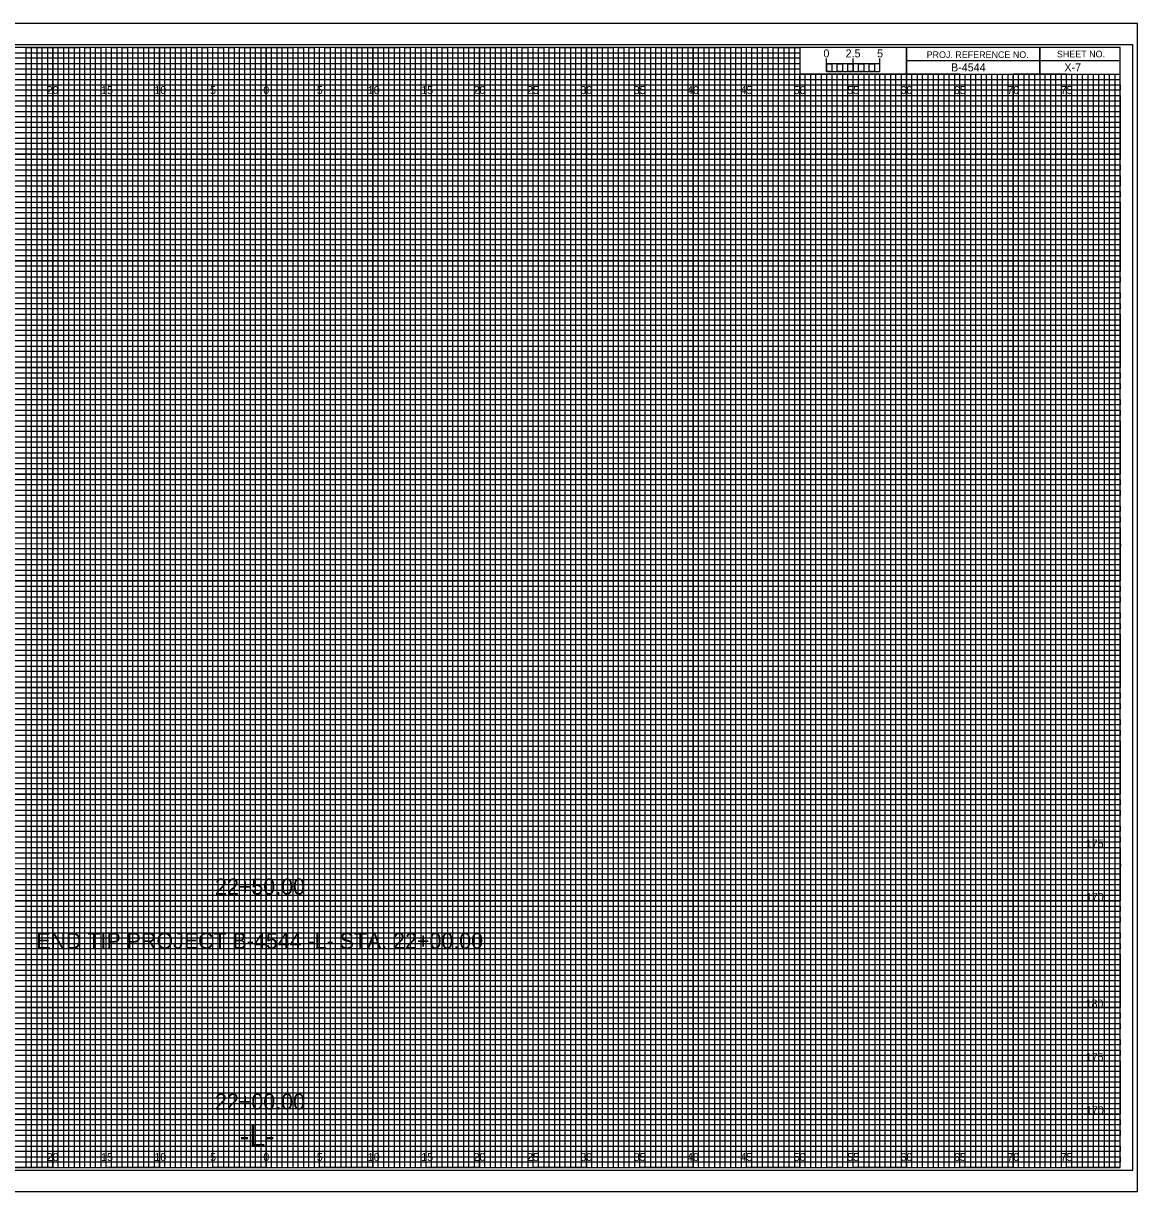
# Model space of a CAD drawing. Extents: x -7 to 162, y -2 to 767.
# Drawn here: x 57.2 to 161.7, y 657.8 to 767.2 of the extents above; entities that cross this region are included whole.
import ezdxf

# ---------------------------------------------------------------- set-up
doc = ezdxf.new("R2010")
doc.units = 0
for name, color, linetype in [('Exist CMT Pavement', 7, 'Continuous'), ('Exist Cross Section Cell', 7, 'Continuous'), ('Exist XS Ground Line', 7, 'Continuous'), ('Prop CMT Pvmt Course 1', 7, 'Continuous'), ('Prop CMT Pvmt Course 1 Wedge', 7, 'Continuous'), ('Prop CMT Pvmt Course 2', 7, 'Continuous'), ('Prop CMT Pvmt Course 2 Wedge', 7, 'Continuous'), ('Prop CMT Pvmt Course 3', 7, 'Continuous'), ('Prop CMT Pvmt Course 3 Wedge', 7, 'Continuous'), ('Prop CMT Pvmt Surface', 7, 'Continuous'), ('Prop CMT Pvmt Surface Shoulder', 7, 'Continuous'), ('Prop CMT Shld Paved Course 1', 7, 'Continuous'), ('Prop CMT Shld Paved Course 2', 7, 'Continuous'), ('Prop CMT Shld Paved Course 3', 7, 'Continuous'), ('Prop CMT Slope Grass', 7, 'Continuous'), ('Prop CMT Subgrade Earthwork', 7, 'Continuous'), ('Scratch_Level_0', 7, 'Continuous')]:
    doc.layers.add(name, color=color, linetype=linetype)

msp = doc.modelspace()

# ---------------------------------------------------------------- linework, layer by layer
at = {"layer": 'Prop CMT Pvmt Course 1'}
for p, q in [((0, 764.5), (130, 764.5)), ((130, 764.5), (130, 763.99)), ((130, 763.99), (0, 763.99)), ((0, 763.5), (130, 763.5)), ((130, 763.5), (130, 762.95)), ((130, 762.95), (0, 762.95)), ((0, 762), (160, 762))]:
    msp.add_line(p, q, dxfattribs=at)
for points in [[(0, 761.5), (135, 761.5), (160, 761.5), (160, 761), (0, 761)], [(0, 760.5), (160, 760.5), (160, 759.5), (0, 759.5)], [(0, 759), (160, 759), (160, 758.5), (0, 758.49)], [(0, 758), (160, 758), (160, 757), (0, 757)], [(0, 756.5), (160, 756.5), (160, 756), (0, 756)], [(0, 755.5), (160, 755.5), (160, 754.5), (0, 754.5)], [(0, 754), (160, 754), (160, 753.5), (0, 753.5)], [(0, 753), (160, 753), (160, 752), (0, 752)], [(0, 751.5), (160, 751.5), (160, 751), (0, 751)], [(0, 750.5), (160, 750.5), (160, 749.5), (0, 749.5)], [(0, 749), (160, 749), (160, 748.5), (0, 748.5)], [(0, 748), (160, 748), (160, 746.98), (160, 746.5), (160, 746), (0, 746)], [(0, 747), (160, 747), (160, 746.5), (0, 746.5)], [(0, 745.5), (160, 745.5), (160, 744.5), (0, 744.51)], [(0, 744.51), (160, 744.5), (160, 744), (0, 744)], [(0, 743.5), (160, 743.5), (160, 743), (0, 743)], [(0, 742), (160, 742), (160, 741.5), (0, 741.5)], [(0, 741), (160, 741), (160, 740.5), (0, 740.5)], [(-0.04, 739.45), (160, 739.45), (160, 738.94), (-0.04, 738.94)], [(0, 738.5), (160, 738.5), (160, 738), (0, 738)], [(0, 737), (160, 737), (160, 736.5), (0, 736.5)], [(0, 736), (160, 736), (160, 735.5), (0, 735.5)], [(0, 734.5), (160, 734.5), (160, 734), (0, 734)], [(0, 733.5), (160, 733.5), (160, 733), (0, 733)], [(0, 732), (160, 732), (160, 731.5), (0, 731.5)], [(0, 731), (160, 731), (160, 730.5), (0, 730.5)], [(0, 729.5), (160, 729.5), (160, 728.99), (0, 729)], [(0, 728.5), (160, 728.5), (160, 728), (0, 728)], [(0, 727), (160, 727), (160, 726.5), (0, 726.5)], [(0, 726), (160, 726), (160, 725.5), (0, 725.5)], [(0, 724.5), (160, 724.5), (160, 724), (0, 724)], [(0, 723.5), (160, 723.5), (160, 723), (0, 723)], [(0, 722), (160, 722), (160, 721.5), (0, 721.5)], [(0, 721), (160, 721), (160, 720.5), (0, 720.5)], [(0, 719.5), (160, 719.5), (160, 719), (0, 719)], [(0, 718.5), (160.03, 718.46), (160, 718), (0, 718)], [(0, 717), (160, 717), (160, 716.5), (0, 716.5)], [(0, 716), (160, 716), (160, 715.5), (0, 715.5)], [(0, 714.5), (160, 714.5), (160, 714), (0, 714)], [(0, 713.5), (160, 713.5), (160, 713), (0, 713)], [(0, 712), (160, 712), (160, 711.5), (0, 711.5)], [(0, 711), (160, 711), (160, 710.5), (0, 710.5)], [(0, 709.5), (160, 709.5), (160, 709), (0, 709)], [(0, 708.5), (160, 708.5), (160, 708), (0, 708)], [(0, 707), (160, 707), (160, 706.5), (0, 706.5)], [(0, 706), (160, 706), (160, 705.5), (0, 705.5)], [(0, 704.5), (160, 704.5), (160, 704), (0, 704)], [(0, 703.5), (160, 703.5), (160, 703), (0, 703)], [(0, 702), (160, 702), (160, 701.5), (0, 701.5)], [(0, 701), (160, 701), (160, 700.5), (0, 700.5)], [(0, 699.5), (160, 699.5), (160, 698.99), (0, 699)], [(0, 698.5), (160, 698.5), (160, 698), (0, 698)], [(0, 697), (160, 697), (160, 696.5), (0, 696.5)], [(0, 696), (160, 696), (160, 695.5), (0, 695.5)], [(0, 694.5), (160, 694.5), (160, 694), (0, 694)], [(0, 693.5), (160, 693.5), (160, 693), (0, 693)], [(0, 692), (160, 692), (160, 691.5), (0, 691.5)], [(0, 691), (160, 691), (160, 690.5), (0, 690.5)], [(0, 689.5), (160, 689.5), (160, 689), (0, 689)], [(0, 688.5), (160.03, 688.46), (160, 688), (0, 688)], [(0, 687), (160, 687), (160, 686.5), (0, 686.5)], [(0, 686), (160, 686), (160, 685.5), (0, 685.5)], [(0, 684.5), (160, 684.5), (160, 684), (0, 684)], [(0, 683.5), (160, 683.5), (160, 683), (0, 683)], [(0, 682), (160, 682), (160, 681.5), (0, 681.5)], [(0, 681), (160, 681), (160, 680.5), (0, 680.5)], [(0, 679.5), (160, 679.5), (160, 679), (0, 679)], [(0, 678.5), (160, 678.5), (160, 678), (0, 678)], [(0, 677), (160, 677), (160, 676.5), (0, 676.5)], [(0, 676), (160, 676), (160, 675.5), (0, 675.5)], [(0, 674.5), (160, 674.5), (160, 674), (0, 674)], [(0, 673.5), (160, 673.5), (160, 673), (0, 673)], [(0, 672), (160, 672), (160, 671.5), (0, 671.5)], [(0, 671), (160, 671), (160, 670.5), (0, 670.5)], [(0, 669.5), (160, 669.5), (160, 669), (0, 669)], [(0, 668.5), (160, 668.5), (160, 668), (0, 668)], [(0, 667), (160, 667), (160, 666.5), (0, 666.5)], [(0, 666), (160, 666), (160, 665.5), (0, 665.5)], [(0, 664.5), (160, 664.5), (160, 664), (0, 664)], [(0, 663.5), (160, 663.5), (160, 663), (0, 663)], [(0, 662), (160, 662), (160, 661.5), (0, 661.5)], [(0, 661), (160, 661), (160, 660.5), (0, 660.5)]]:
    msp.add_lwpolyline(points, dxfattribs=at)
at = {"layer": 'Prop CMT Pvmt Course 2'}
for p, q in [((60, 660), (60, 765)), ((65, 660), (65, 765)), ((70, 660), (70, 765)), ((75, 660), (75, 765)), ((80, 660), (80, 765)), ((85, 660), (85, 765)), ((90, 660), (90, 765)), ((95, 660), (95, 765)), ((100, 660), (100, 765)), ((105, 660), (105, 765)), ((110, 660), (110, 765)), ((115, 660), (115, 765)), ((120, 660), (120, 765)), ((125, 660), (125, 765)), ((130, 660), (130, 762.34)), ((135, 660), (135, 762.34)), ((140, 660), (140, 762.34)), ((145, 660), (145, 762.34)), ((150, 660), (150, 762.34)), ((155, 660), (155, 762.34)), ((0, 760), (160, 760)), ((0, 755), (160, 755)), ((0, 750), (160, 750)), ((0, 745), (160, 745)), ((0, 740), (160, 740)), ((0, 735), (160, 735)), ((0, 730), (160, 730)), ((0, 725), (160, 725)), ((0, 720), (160, 720)), ((0, 715), (160, 715)), ((0, 710), (160, 710)), ((0, 705), (160, 705)), ((0, 700), (160, 700)), ((0, 695), (160, 695)), ((0, 690), (160, 690)), ((0, 685), (160, 685)), ((0, 680), (160, 680)), ((0, 675), (160, 675)), ((0, 670), (160, 670)), ((0, 665), (160, 665))]:
    msp.add_line(p, q, dxfattribs=at)
at = {"layer": 'Prop CMT Pvmt Course 3'}
for p, q in [((161.65, 767.25), (-6.7, 767.25)), ((-6.7, 657.75), (161.65, 657.75))]:
    msp.add_line(p, q, dxfattribs=at)
at = {"layer": 'Prop CMT Pvmt Surface Shoulder'}
for points in [[(52.5, 660), (57.5, 660), (57.5, 765), (62.5, 765), (62.5, 660), (67.5, 660), (67.5, 765), (72.5, 765), (72.5, 660), (77.5, 660), (77.5, 765), (82.5, 765), (82.5, 660), (87.5, 660), (87.5, 765), (92.5, 765), (92.5, 660), (97.5, 660), (97.5, 765), (102.5, 765), (102.5, 660), (107.5, 660), (107.5, 765), (112.5, 765), (112.5, 660), (117.5, 660), (117.5, 765), (122.5, 765), (122.5, 660), (127.5, 660), (127.5, 765), (129.97, 765), (130, 765), (130, 762.5), (132.5, 762.5), (132.5, 660), (137.5, 660), (137.5, 762.5), (142.5, 762.5), (142.5, 660), (147.5, 660), (147.5, 762.5), (152.5, 762.5), (152.5, 660), (157.5, 660), (157.5, 762.5)], [(0, 762.5), (137.5, 762.5)], [(0, 752.5), (160, 752.5), (160, 757.5), (0, 757.5)], [(0, 742.5), (160, 742.5), (160, 747.5), (0, 747.5)], [(0, 732.5), (160, 732.5), (160, 737.5), (0, 737.5)], [(0, 722.5), (160, 722.5), (160, 727.5), (0, 727.5)], [(0, 712.5), (160, 712.5), (160, 717.5), (0, 717.5)], [(0, 702.5), (160, 702.5), (160, 707.5), (0, 707.5)], [(0, 692.5), (160, 692.5), (160, 697.5), (0, 697.5)], [(0, 682.5), (160, 682.5), (160, 687.5), (0, 687.5)], [(0, 672.5), (160, 672.5), (160, 677.5), (0, 677.5)], [(0, 662.5), (160, 662.5), (160, 667.5), (0, 667.5)]]:
    msp.add_lwpolyline(points, dxfattribs=at)
at = {"layer": 'Prop CMT Shld Paved Course 1'}
for p, q in [((132.5, 762.75), (132.5, 763.95)), ((132.5, 763.45), (132.5, 763.95)), ((135, 762.75), (135, 763.95)), ((137.5, 762.75), (137.5, 763.95)), ((137.5, 763.45), (137.5, 763.95))]:
    msp.add_line(p, q, dxfattribs=at)
for points in [[(137.5, 763.45), (132.5, 763.45), (132.5, 762.75), (137.5, 762.75)], [(132.5, 763.45), (133, 763.45), (133, 762.75), (132.5, 762.75)], [(133.5, 763.45), (134, 763.45), (134, 762.75), (133.5, 762.75)], [(134.5, 763.45), (135, 763.45), (135, 762.75), (134.5, 762.75)], [(135.5, 763.45), (136, 763.45), (136, 762.75), (135.5, 762.75)], [(136.5, 763.45), (137, 763.45), (137, 762.75), (136.5, 762.75)]]:
    msp.add_lwpolyline(points, close=True, dxfattribs=at)
at = {"layer": 'Prop CMT Shld Paved Course 2'}
msp.add_lwpolyline([(-6.7, 657.75), (161.65, 657.75), (161.65, 767.25), (-6.7, 767.25)], close=True, dxfattribs=at)
at = {"layer": 'Prop CMT Shld Paved Course 3'}
msp.add_lwpolyline([(-5.4, 659.75), (161.2, 659.75), (161.2, 765.25), (-5.4, 765.25)], close=True, dxfattribs=at)
at = {"layer": 'Prop CMT Slope Grass'}
for p, q in [((133.5, 762.5), (133, 762.5)), ((133, 762.5), (133, 660)), ((133.5, 660), (133.5, 762.5)), ((134.5, 762.5), (134, 762.5)), ((134, 762.5), (134, 660)), ((134.5, 660), (134.5, 762.5)), ((133, 660), (132.5, 660)), ((134, 660), (133.5, 660))]:
    msp.add_line(p, q, dxfattribs=at)
for points in [[(57.5, 660), (58, 660), (58, 765), (58.5, 765), (58.5, 660)], [(58.5, 660), (59, 660), (59, 765), (59.5, 765), (59.5, 660)], [(60, 660), (60.5, 660), (60.5, 765), (61, 765), (61, 660)], [(61, 660), (61.5, 660), (61.5, 765), (62, 765), (62, 660)], [(62.5, 660), (63, 660), (63, 765), (63.5, 765), (63.5, 660)], [(63.5, 660), (64, 660), (64, 765), (64.5, 765), (64.5, 660)], [(65, 660), (65.5, 660), (65.5, 765), (66, 765), (66, 660)], [(66, 660), (66.5, 660), (66.5, 765), (67, 765), (67, 660)], [(67.5, 660), (68, 660), (68, 765), (68.5, 765), (68.5, 660)], [(68.5, 660), (69, 660), (69, 765), (69.5, 765), (69.5, 660)], [(70, 660), (70.5, 660), (70.5, 765), (71, 765), (71, 660)], [(71, 660), (71.5, 660), (71.5, 765), (72, 765), (72, 660)], [(72.5, 660), (73, 660), (73, 765), (73.5, 765), (73.5, 660)], [(73.5, 660), (74, 660), (74, 765), (74.5, 765), (74.5, 660)], [(75, 660), (75.5, 660), (75.5, 765), (76, 765), (76, 660)], [(76, 660), (76.5, 660), (76.5, 765), (77, 765), (77, 660)], [(77.5, 660), (78, 660), (78, 765), (78.5, 765), (78.5, 660)], [(78.5, 660), (79, 660), (79, 765), (79.5, 765), (79.5, 660)], [(80, 660), (80.5, 660), (80.5, 765), (81, 765), (81, 660)], [(81, 660), (81.5, 660), (81.5, 765), (82, 765), (82, 660)], [(82.5, 660), (83, 660), (83, 765), (83.5, 765), (83.5, 660)], [(83.5, 660), (84, 660), (84, 765), (84.5, 765), (84.5, 660)], [(85, 660), (85.5, 660), (85.5, 765), (86, 765), (86, 660)], [(86, 660), (86.5, 660), (86.5, 765), (87, 765), (87, 660)], [(87.5, 660), (88, 660), (88, 765), (88.5, 765), (88.5, 660)], [(88.5, 660), (89, 660), (89, 765), (89.5, 765), (89.5, 660)], [(90, 660), (90.5, 660), (90.5, 765), (91, 765), (91, 660)], [(91, 660), (91.5, 660), (91.5, 765), (92, 765), (92, 660)], [(92.5, 660), (93, 660), (93, 765), (93.5, 765), (93.5, 660)], [(93.5, 660), (94, 660), (94, 765), (94.5, 765), (94.5, 660)], [(95, 660), (95.5, 660), (95.5, 765), (96, 765), (96, 660)], [(96, 660), (96.5, 660), (96.5, 765), (97, 765), (97, 660)], [(97.5, 660), (98, 660), (98, 765), (98.5, 765), (98.5, 660)], [(98.5, 660), (99, 660), (99, 765), (99.5, 765), (99.5, 660)], [(100, 660), (100.5, 660), (100.5, 765), (101, 765), (101, 660)], [(101, 660), (101.5, 660), (101.5, 765), (102, 765), (102, 660)], [(102.5, 660), (103, 660), (103, 765), (103.5, 765), (103.5, 660)], [(103.5, 660), (104, 660), (104, 765), (104.5, 765), (104.5, 660)], [(105, 660), (105.5, 660), (105.5, 765), (106, 765), (106, 660)], [(106, 660), (106.5, 660), (106.5, 765), (107, 765), (107, 660)], [(107.5, 660), (108, 660), (108, 765), (108.5, 765), (108.5, 660)], [(108.5, 660), (109, 660), (109, 765), (109.5, 765), (109.5, 660)], [(110, 660), (110.5, 660), (110.5, 765), (111, 765), (111, 660)], [(111, 660), (111.5, 660), (111.5, 765), (112, 765), (112, 660)], [(112.5, 660), (113, 660), (113, 765), (113.5, 765), (113.5, 660)], [(113.5, 660), (114, 660), (114, 765), (114.5, 765), (114.5, 660)], [(115, 660), (115.5, 660), (115.5, 765), (116, 765), (116, 660)], [(116, 660), (116.5, 660), (116.5, 765), (117, 765), (117, 660)], [(117.5, 660), (118, 660), (118, 765), (118.5, 765), (118.5, 660)], [(118.5, 660), (119, 660), (119, 765), (119.5, 765), (119.5, 660)], [(120, 660), (120.5, 660), (120.5, 765), (121, 765), (121, 660)], [(121, 660), (121.5, 660), (121.5, 765), (122, 765), (122, 660)], [(122.5, 660), (123, 660), (123, 765), (123.5, 765), (123.5, 660)], [(123.5, 660), (124, 660), (124, 765), (124.5, 765), (124.5, 660)], [(125, 660), (125.5, 660), (125.5, 765), (126, 765), (126, 660)], [(126, 660), (126.5, 660), (126.5, 765), (127, 765), (127, 660)], [(127.5, 660), (128, 660), (128, 765), (128.5, 765), (128.5, 660)], [(128.5, 660), (129, 660), (129, 765), (129.5, 765), (129.5, 660)], [(130, 660), (130.5, 660), (130.5, 762.5), (131.01, 762.5), (131.01, 660)], [(131, 660), (131.5, 660), (131.5, 762.5), (132, 762.5), (132, 660)], [(135, 660), (135.49, 660), (135.49, 762.5), (136, 762.5), (136, 660)], [(136, 660), (136.5, 660), (136.5, 762.5), (137.03, 762.5), (137.03, 660)], [(137.5, 660), (138, 660), (138, 762.5), (138.5, 762.5), (138.5, 660)], [(138.5, 660), (139, 660), (139, 762.5), (139.5, 762.5), (139.5, 660)], [(140, 660), (140.5, 660), (140.5, 762.5), (141, 762.5), (141, 660)], [(141, 660), (141.5, 660), (141.5, 762.5), (142, 762.5), (142, 660)], [(142.5, 660), (143, 660), (143, 762.5), (143.5, 762.5), (143.5, 660)], [(143.5, 660), (144, 660), (144, 762.5), (144.5, 762.5), (144.5, 660)], [(145, 660), (145.5, 660), (145.5, 762.5), (146, 762.5), (146, 660)], [(146, 660), (146.5, 660), (146.5, 762.5), (147, 762.5), (147, 660)], [(147.5, 660), (148, 660), (148, 762.5), (148.5, 762.5), (148.5, 660)], [(148.5, 660), (149, 660), (149, 762.5), (149.5, 762.5), (149.5, 660)], [(150, 660), (150.5, 660), (150.5, 762.5), (151, 762.5), (151, 660)], [(151, 660), (151.5, 660), (151.5, 762.5), (152, 762.5), (152, 660)], [(152.5, 660), (153, 660), (153, 762.5), (153.5, 762.5), (153.5, 660)], [(153.5, 660), (154, 660), (154, 762.5), (154.5, 762.5), (154.5, 660)], [(155, 660), (155.5, 660), (155.5, 762.5), (156, 762.5), (156, 660)], [(156, 660), (156.5, 660), (156.5, 762.5), (157, 762.5), (157, 660)], [(157.5, 660), (158, 660), (158, 762.5), (158.5, 762.5), (158.5, 660)], [(158.5, 660), (159, 660), (159, 762.5), (159.5, 762.5), (159.5, 660)]]:
    msp.add_lwpolyline(points, dxfattribs=at)
at = {"layer": 'Prop CMT Subgrade Earthwork'}
for p, q in [((152.5, 765), (152.5, 762.5)), ((152.5, 762.5), (152.5, 765)), ((160, 763.75), (140, 763.75)), ((140, 763.75), (140, 762.5)), ((140, 762.5), (160, 762.5))]:
    msp.add_line(p, q, dxfattribs=at)
for points in [[(160, 765), (0, 765), (0, 660), (160, 660)], [(140, 765), (130, 765), (130, 762.51), (140, 762.51)], [(160, 765), (140, 765), (140, 762.5), (160, 762.5)]]:
    msp.add_lwpolyline(points, close=True, dxfattribs=at)
at = {"layer": 'Scratch_Level_0'}
for p, q in [((65, 765), (60, 765)), ((60, 765), (60, 660)), ((65, 660), (65, 765)), ((75, 765), (70, 765)), ((70, 765), (70, 660)), ((75, 660), (75, 765)), ((85, 765), (80, 765)), ((80, 765), (80, 660)), ((85, 660), (85, 765)), ((95, 765), (90, 765)), ((90, 765), (90, 660)), ((95, 660), (95, 765)), ((105, 765), (100, 765)), ((100, 765), (100, 660)), ((105, 660), (105, 765)), ((115, 765), (110, 765)), ((110, 765), (110, 660)), ((115, 660), (115, 765)), ((125, 765), (120, 765)), ((120, 765), (120, 660)), ((125, 660), (125, 765)), ((130, 765), (130, 660)), ((135, 660), (135, 762.5)), ((145, 762.5), (140, 762.5)), ((140, 762.5), (140, 660)), ((145, 660), (145, 762.5)), ((155, 762.5), (150, 762.5)), ((150, 762.5), (150, 660)), ((155, 660), (155, 762.5)), ((60, 660), (55, 660)), ((70, 660), (65, 660)), ((80, 660), (75, 660)), ((90, 660), (85, 660)), ((100, 660), (95, 660)), ((110, 660), (105, 660)), ((120, 660), (115, 660)), ((130, 660), (125, 660)), ((140, 660), (135, 660)), ((150, 660), (145, 660)), ((160, 660), (155, 660)), ((160, 660), (160, 660))]:
    msp.add_line(p, q, dxfattribs=at)
for points in [[(0, 760), (160, 760), (160, 755), (0, 755)], [(0, 750), (160, 750), (160, 745), (0, 745)], [(0, 740), (160, 740), (160, 735), (0, 735)], [(0, 730), (160, 730), (160, 725), (0, 725)], [(0, 720), (160, 720), (160, 715), (0, 715)], [(0, 710), (160, 710), (160, 705), (0, 705)], [(0, 700), (160, 700), (160, 695), (0, 695)], [(0, 690), (160, 690), (160, 685), (0, 685)], [(0, 680), (160, 680), (160, 675), (0, 675)], [(0, 670), (160, 670), (160, 665), (0, 665)]]:
    msp.add_lwpolyline(points, dxfattribs=at)

# ---------------------------------------------------------------- texts
at = {"layer": 'Exist CMT Pavement'}
msp.add_text('B-4544', height=0.75, dxfattribs=at).set_placement((144.17, 762.75))
at = {"layer": 'Exist Cross Section Cell'}
for s, p in [('20', (59.43, 760.62)), ('15', (64.53, 760.62)), ('10', (69.52, 760.62)), ('5', (74.74, 760.62)), ('0', (79.73, 760.62)), ('0', (79.73, 760.62)), ('5', (84.74, 760.62)), ('10', (89.52, 760.62)), ('15', (94.53, 760.62)), ('20', (99.43, 760.62)), ('25', (104.44, 760.62)), ('30', (109.43, 760.62)), ('35', (114.44, 760.62)), ('40', (119.43, 760.62)), ('45', (124.44, 760.62)), ('50', (129.43, 760.62)), ('55', (134.44, 760.62)), ('60', (139.43, 760.62)), ('65', (144.44, 760.62)), ('70', (149.43, 760.62)), ('75', (154.44, 760.62)), ('20', (59.43, 660.62)), ('10', (69.52, 660.62)), ('0', (79.73, 660.62)), ('0', (79.73, 660.62)), ('10', (89.52, 660.62)), ('20', (99.43, 660.62)), ('25', (104.44, 660.62)), ('30', (109.43, 660.62)), ('35', (114.44, 660.62)), ('40', (119.43, 660.62)), ('50', (129.43, 660.62)), ('60', (139.43, 660.62)), ('65', (144.44, 660.62)), ('70', (149.43, 660.62)), ('15', (64.53, 660.62)), ('5', (74.74, 660.62)), ('5', (84.74, 660.62)), ('15', (94.53, 660.62)), ('45', (124.44, 660.62)), ('55', (134.44, 660.62)), ('75', (154.44, 660.62))]:
    msp.add_text(s, height=0.75, dxfattribs=at).set_placement(p)
at = {"layer": 'Exist XS Ground Line'}
for s, p in [('2.5', (134.29, 764.06)), ('5', (137.24, 764.06))]:
    msp.add_text(s, height=0.75, dxfattribs=at).set_placement(p)
at = {"layer": 'Prop CMT Pvmt Course 1 Wedge'}
for s, p in [('175', (156.79, 690)), ('170', (156.8, 685)), ('180', (156.77, 675)), ('175', (156.79, 670)), ('170', (156.8, 665))]:
    msp.add_text(s, height=0.75, dxfattribs=at).set_placement(p)
at = {"layer": 'Prop CMT Pvmt Course 2 Wedge'}
for s, p in [('22+50.00', (75.21, 685.59)), ('END TIP PROJECT B-4544 -L- STA. 22+00.00', (58.46, 680.51)), ('22+00.00', (75.21, 665.44))]:
    msp.add_text(s, height=1.5, dxfattribs=at).set_placement(p)
at = {"layer": 'Prop CMT Pvmt Course 3 Wedge'}
msp.add_text('X-7', height=0.75, dxfattribs=at).set_placement((154.79, 762.75))
at = {"layer": 'Prop CMT Pvmt Surface'}
msp.add_text('-L-', height=2, dxfattribs=at).set_placement((77.53, 662))
at = {"layer": 'Prop CMT Shld Paved Course 1'}
msp.add_text('0', height=0.75, dxfattribs=at).set_placement((132.21, 764.06))
at = {"layer": 'Prop CMT Subgrade Earthwork'}
for s, p in [('PROJ. REFERENCE NO.', (141.88, 764)), ('SHEET NO.', (154.09, 764.06))]:
    msp.add_text(s, height=0.625, dxfattribs=at).set_placement(p)

doc.saveas('drawing.dxf')
